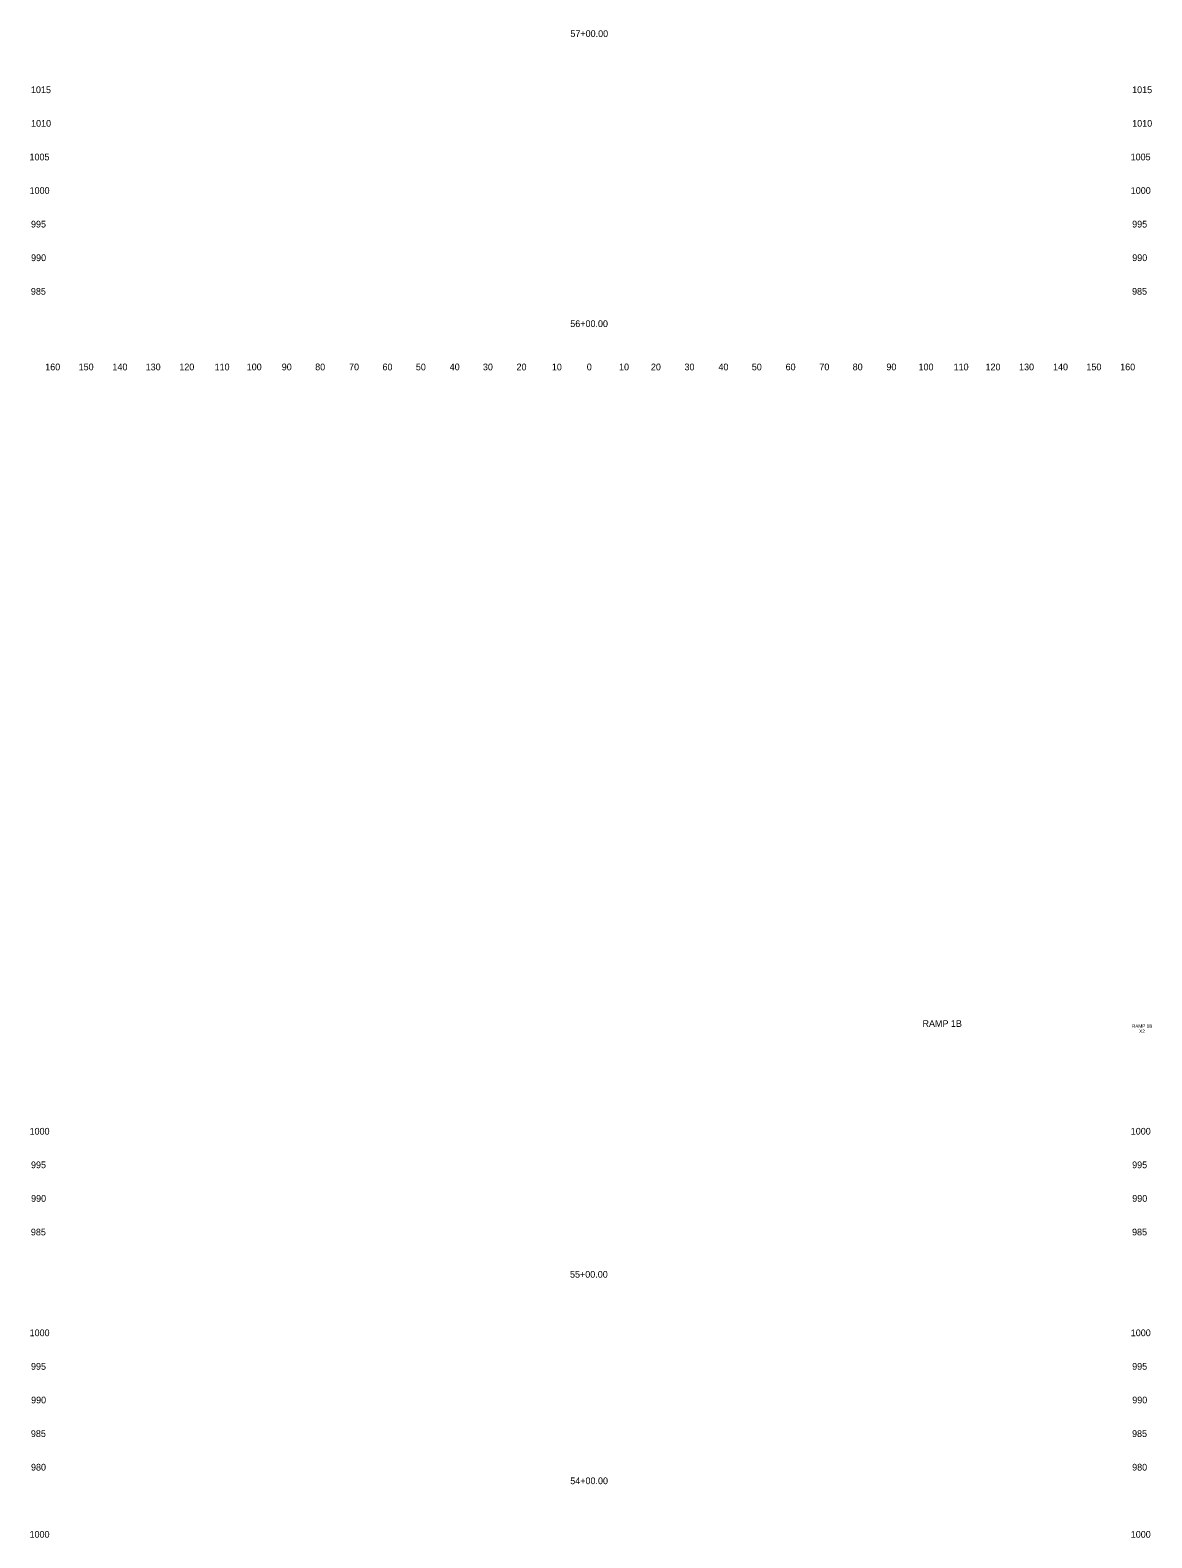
# Model space of a CAD drawing. Extents: x 4994 to 5843, y 4997 to 8804.
# Drawn here: x 4993.6 to 5327.5, y 5450 to 5898.7 of the extents above; entities that cross this region are included whole.
import ezdxf

# ---------------------------------------------------------------- set-up
doc = ezdxf.new("R2010")
doc.units = 0
for name, color, linetype in [('CLS_Search_Dist', 7, 'Continuous'), ('RD_XE_Ground', 7, 'Continuous'), ('UC_PD_Text', 7, 'Continuous')]:
    doc.layers.add(name, color=color, linetype=linetype)

msp = doc.modelspace()

# ---------------------------------------------------------------- texts
at = {"layer": 'CLS_Search_Dist'}
for s, p in [('1015', (4993.85, 5880)), ('1015', (5321.65, 5880)), ('1010', (4993.88, 5870)), ('1010', (5321.68, 5870)), ('1005', (4993.4, 5860)), ('1005', (5321.2, 5860)), ('1000', (4993.44, 5850)), ('1000', (5321.24, 5850)), ('995', (4993.86, 5840)), ('995', (5321.66, 5840)), ('990', (4993.89, 5830)), ('990', (5321.69, 5830)), ('985', (4993.83, 5820)), ('985', (5321.63, 5820)), ('160', (4998.1, 5797.5)), ('150', (5008.04, 5797.5)), ('140', (5018.1, 5797.5)), ('130', (5027.99, 5797.5)), ('120', (5038.01, 5797.5)), ('110', (5048.51, 5797.5)), ('100', (5058.07, 5797.5)), ('90', (5068.5, 5797.5)), ('80', (5078.46, 5797.5)), ('70', (5088.54, 5797.5)), ('60', (5098.5, 5797.5)), ('50', (5108.43, 5797.5)), ('40', (5118.5, 5797.5)), ('30', (5128.39, 5797.5)), ('20', (5138.4, 5797.5)), ('10', (5148.91, 5797.5)), ('0', (5159.3, 5797.5)), ('0', (5159.3, 5797.5)), ('10', (5168.91, 5797.5)), ('20', (5178.4, 5797.5)), ('30', (5188.39, 5797.5)), ('40', (5198.5, 5797.5)), ('50', (5208.43, 5797.5)), ('60', (5218.5, 5797.5)), ('70', (5228.54, 5797.5)), ('80', (5238.46, 5797.5)), ('90', (5248.5, 5797.5)), ('100', (5258.07, 5797.5)), ('110', (5268.51, 5797.5)), ('120', (5278.01, 5797.5)), ('130', (5287.99, 5797.5)), ('140', (5298.1, 5797.5)), ('150', (5308.04, 5797.5)), ('160', (5318.1, 5797.5)), ('1000', (4993.44, 5570)), ('1000', (5321.24, 5570)), ('995', (4993.86, 5560)), ('995', (5321.66, 5560)), ('990', (4993.89, 5550)), ('990', (5321.69, 5550)), ('985', (4993.83, 5540)), ('985', (5321.63, 5540)), ('1000', (4993.44, 5510)), ('1000', (5321.24, 5510)), ('995', (4993.86, 5500)), ('995', (5321.66, 5500)), ('990', (4993.89, 5490)), ('990', (5321.69, 5490)), ('985', (4993.83, 5480)), ('985', (5321.63, 5480)), ('980', (4993.86, 5470)), ('980', (5321.66, 5470)), ('1000', (4993.44, 5450)), ('1000', (5321.24, 5450))]:
    msp.add_text(s, height=2, dxfattribs=at).set_placement(p)
at = {"layer": 'RD_XE_Ground'}
for s, p in [('57+00.00', (5154.43, 5896.71)), ('56+00.00', (5154.39, 5810.37)), ('55+00.00', (5154.32, 5527.4)), ('54+00.00', (5154.39, 5465.95))]:
    msp.add_text(s, height=2, dxfattribs=at).set_placement(p)
at = {"layer": 'UC_PD_Text'}
for s, height, p in [('RAMP 1B', 2, (5259.24, 5602.06)), ('RAMP 1B', 1, (5321.59, 5601.8)), ('X2', 1, (5323.74, 5600.3))]:
    msp.add_text(s, height=height, dxfattribs=at).set_placement(p)

doc.saveas('drawing.dxf')
